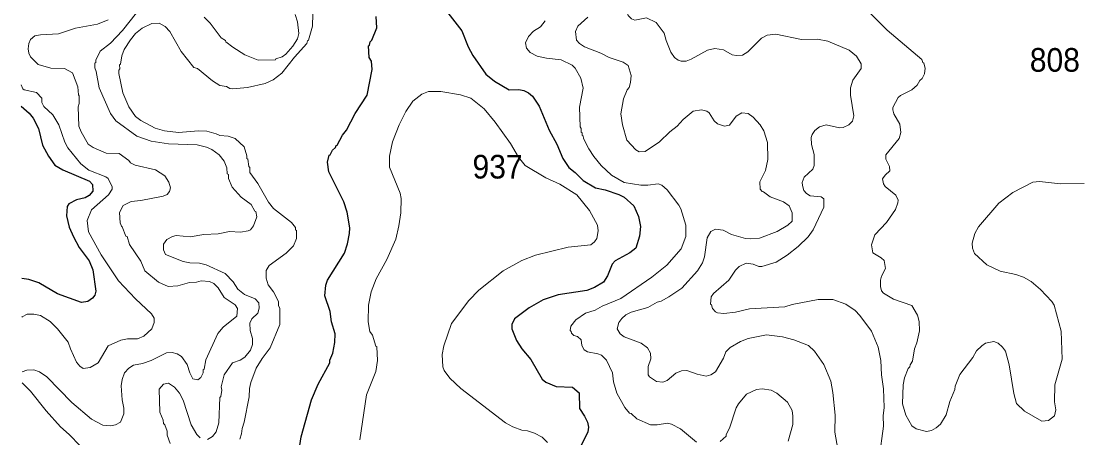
# Model space of a CAD drawing. Extents: x 447.8 to 473.9, y 7733.1 to 7760.8.
# Drawn here: x 447.796 to 451.389, y 7753.347 to 7754.756 of the extents above; entities that cross this region are included whole.
import ezdxf

# ---------------------------------------------------------------- set-up
doc = ezdxf.new("R2010")
doc.units = 0
doc.header["$LTSCALE"] = 0.032
doc.layers.add('1', color=7, linetype='Continuous', lineweight=25)
doc.layers.add('2', color=7, linetype='Continuous', lineweight=13)
doc.layers.add('21', color=7, linetype='Continuous')

msp = doc.modelspace()

# ---------------------------------------------------------------- linework, layer by layer
at = {"layer": '1'}
for points in [[(449.2047, 7754.832), (449.2874, 7754.724), (449.309, 7754.67), (449.325, 7754.6405), (449.3687, 7754.5776), (449.3987, 7754.5529), (449.4484, 7754.5245), (449.4803, 7754.5252), (449.4977, 7754.5213), (449.5137, 7754.5134), (449.5265, 7754.5021), (449.5489, 7754.469), (449.5831, 7754.3878), (449.6096, 7754.3397), (449.6296, 7754.2916), (449.65, 7754.2618), (449.6712, 7754.2446), (449.6981, 7754.2169), (449.7403, 7754.1925), (449.7729, 7754.1859), (449.8195, 7754.1704), (449.8368, 7754.1609), (449.8695, 7754.1313), (449.8858, 7754.0951), (449.8922, 7754.0613), (449.8891, 7754.029), (449.8762, 7753.9882), (449.8558, 7753.9731), (449.8069, 7753.9458), (449.7964, 7753.9339), (449.7805, 7753.8951)], [(448.7366, 7753.2995), (448.7445, 7753.3506), (448.7791, 7753.4747), (448.8013, 7753.5286), (448.8406, 7753.6001), (448.8408, 7753.6098), (448.8511, 7753.633), (448.8584, 7753.6687), (448.8591, 7753.6985), (448.8471, 7753.7392), (448.8424, 7753.7738), (448.8246, 7753.8273), (448.8279, 7753.8627), (448.8328, 7753.8802), (448.8903, 7753.9714), (448.9008, 7754.0034), (448.908, 7754.0383), (448.9088, 7754.0567), (448.8998, 7754.11), (448.8878, 7754.1447), (448.8375, 7754.2471), (448.8335, 7754.2794), (448.8392, 7754.303), (448.8424, 7754.3044), (448.8504, 7754.3198), (448.8601, 7754.3287), (448.8623, 7754.3356), (448.8655, 7754.3364), (448.8838, 7754.3702), (448.8973, 7754.3881), (448.9264, 7754.4445), (448.9673, 7754.5055), (448.9841, 7754.5925), (448.982, 7754.6211), (448.9744, 7754.6339), (448.9722, 7754.6731), (448.9753, 7754.6755), (448.977, 7754.6863), (448.9831, 7754.6925), (448.9995, 7754.7342), (448.998, 7754.7722)], [(447.7967, 7754.4686), (447.8232, 7754.4452), (447.8371, 7754.4282), (447.8547, 7754.3929), (447.8682, 7754.337), (447.8884, 7754.2999), (447.91, 7754.2697), (447.9372, 7754.2539), (448.0275, 7754.2151), (448.0374, 7754.2038), (448.0391, 7754.1817), (448.0261, 7754.1669), (448.0134, 7754.159), (447.9839, 7754.1514), (447.9575, 7754.1388), (447.9516, 7754.1292), (447.9494, 7754.0977), (447.9589, 7754.0593), (447.973, 7754.0265), (447.9928, 7753.9911), (448.0262, 7753.9457), (448.039, 7753.9155), (448.0495, 7753.8434), (448.0461, 7753.8292), (448.0373, 7753.8189), (448.0222, 7753.808), (448.001, 7753.8047), (447.9187, 7753.8339), (447.8556, 7753.8706), (447.8225, 7753.8823), (447.7985, 7753.8852)], [(449.7805, 7753.8951), (449.7674, 7753.8738), (449.7366, 7753.8549), (449.7104, 7753.8448), (449.6138, 7753.8303), (449.5634, 7753.8141)], [(449.5634, 7753.8141), (449.5159, 7753.7861), (449.4662, 7753.7495), (449.4565, 7753.7296), (449.4571, 7753.7156), (449.4727, 7753.6761), (449.4913, 7753.6478), (449.5214, 7753.6119), (449.5595, 7753.5452), (449.5717, 7753.5348), (449.6067, 7753.5201), (449.6626, 7753.5185), (449.6852, 7753.4994), (449.6856, 7753.4459), (449.7034, 7753.4203), (449.7127, 7753.3994), (449.716, 7753.3826), (449.7143, 7753.367), (449.6856, 7753.3097)]]:
    msp.add_lwpolyline(points, dxfattribs=at)
at = {"layer": '2'}
for points in [[(449.9451, 7754.7519), (449.9132, 7754.7673), (449.8731, 7754.7592), (449.8618, 7754.7637), (449.8512, 7754.7755), (449.8467, 7754.7911)], [(448.0909, 7754.7611), (448.0546, 7754.7461), (447.9805, 7754.7322), (447.9226, 7754.7134), (447.8615, 7754.7105), (447.8422, 7754.7064), (447.8279, 7754.6947), (447.8226, 7754.6812), (447.8203, 7754.663), (447.8225, 7754.6485), (447.8282, 7754.6361), (447.8537, 7754.61), (447.8966, 7754.5972), (447.9425, 7754.5965), (447.9702, 7754.5819), (447.9878, 7754.534), (447.9901, 7754.5069), (447.9926, 7754.5041), (447.9926, 7754.478), (447.9895, 7754.4667), (447.9919, 7754.4006), (447.9989, 7754.382), (448.0235, 7754.3405), (448.0397, 7754.3285), (448.084, 7754.3097), (448.1284, 7754.3087), (448.1609, 7754.2847), (448.1667, 7754.2773), (448.1825, 7754.2693), (448.2514, 7754.2535)], [(448.1869, 7754.7844), (448.1388, 7754.7251), (448.099, 7754.6821), (448.0635, 7754.6546), (448.0488, 7754.6243), (448.0487, 7754.6162), (448.0456, 7754.6139), (448.0456, 7754.5983)], [(448.7829, 7754.7814), (448.7822, 7754.7399), (448.7685, 7754.6916), (448.7653, 7754.6899), (448.7628, 7754.6808), (448.721, 7754.6348), (448.6787, 7754.5807), (448.6493, 7754.5578), (448.6221, 7754.5456), (448.5623, 7754.5322), (448.513, 7754.5269), (448.5023, 7754.5286), (448.4909, 7754.5349), (448.4684, 7754.5391), (448.4434, 7754.5541), (448.3926, 7754.5957), (448.381, 7754.5998), (448.3378, 7754.6532), (448.2997, 7754.721), (448.2831, 7754.7382), (448.2638, 7754.7497)], [(448.7237, 7754.7791), (448.7316, 7754.7536), (448.7355, 7754.7142), (448.7313, 7754.6968), (448.7161, 7754.6717), (448.6923, 7754.6449), (448.68, 7754.6357), (448.6581, 7754.6285), (448.657, 7754.6253), (448.5987, 7754.6239), (448.5531, 7754.6426), (448.5126, 7754.668), (448.4893, 7754.6861), (448.4874, 7754.6907), (448.4727, 7754.7001), (448.4365, 7754.7499), (448.4161, 7754.7695)], [(449.6859, 7754.4656), (449.6983, 7754.5296), (449.6902, 7754.5632), (449.6715, 7754.5975), (449.6612, 7754.6071), (449.6237, 7754.626), (449.5743, 7754.6311), (449.5428, 7754.6379), (449.5187, 7754.65), (449.5062, 7754.6645), (449.5037, 7754.6836), (449.5131, 7754.7047), (449.5298, 7754.723), (449.5536, 7754.7372), (449.5697, 7754.7579)], [(449.9156, 7753.6515), (449.8949, 7753.667), (449.8373, 7753.6882), (449.8237, 7753.6987), (449.8138, 7753.715), (449.8192, 7753.7366), (449.8296, 7753.7507), (449.8433, 7753.7623), (449.8606, 7753.7718), (449.917, 7753.7872), (449.9484, 7753.8054), (449.9621, 7753.8095), (449.9888, 7753.824), (450.0323, 7753.8532), (450.0856, 7753.912), (450.102, 7753.9386), (450.1089, 7753.9588), (450.1175, 7754.0236), (450.1305, 7754.0449), (450.1464, 7754.0531), (450.1721, 7754.049), (450.2008, 7754.0344), (450.2479, 7754.0211), (450.2651, 7754.0194), (450.2953, 7754.0224), (450.3546, 7754.0453), (450.3912, 7754.0661), (450.4053, 7754.0793), (450.4052, 7754.1074), (450.3957, 7754.1321), (450.3759, 7754.1447), (450.3312, 7754.162), (450.3086, 7754.1795), (450.3037, 7754.18), (450.2976, 7754.1885), (450.2965, 7754.2125), (450.315, 7754.2508), (450.3236, 7754.2884), (450.322, 7754.3464), (450.3099, 7754.3852), (450.2977, 7754.4061), (450.2742, 7754.432), (450.2568, 7754.4436), (450.2351, 7754.4465), (450.216, 7754.4352), (450.1931, 7754.4044), (450.1771, 7754.401), (450.1534, 7754.4085), (450.1415, 7754.4197), (450.1247, 7754.4466), (450.1168, 7754.4522), (450.0994, 7754.4563), (450.0704, 7754.4514), (450.0366, 7754.4242), (450.0163, 7754.4006), (449.9915, 7754.3815), (449.9562, 7754.3483), (449.9084, 7754.3153), (449.8874, 7754.3138), (449.8764, 7754.3215), (449.8459, 7754.3536), (449.8315, 7754.4055), (449.8259, 7754.4423), (449.835, 7754.4933), (449.847, 7754.5235), (449.8537, 7754.5322), (449.8588, 7754.5491), (449.8604, 7754.5722), (449.8505, 7754.6059), (449.834, 7754.6177), (449.7859, 7754.6337), (449.7577, 7754.6478), (449.7025, 7754.6695), (449.6859, 7754.6812), (449.6756, 7754.6926), (449.6728, 7754.7219), (449.6806, 7754.7398), (449.7144, 7754.7694)], [(450.7004, 7753.2774), (450.7148, 7753.3861), (450.7132, 7753.4214), (450.7173, 7753.4495), (450.7148, 7753.5128), (450.7076, 7753.5603), (450.706, 7753.6087), (450.6971, 7753.6539), (450.6747, 7753.7076), (450.6348, 7753.7611), (450.6192, 7753.7775), (450.5875, 7753.7986), (450.5432, 7753.815), (450.4932, 7753.815), (450.4056, 7753.7975), (450.381, 7753.7901), (450.2608, 7753.7829), (450.2136, 7753.7718), (450.1739, 7753.7678), (450.1525, 7753.77), (450.146, 7753.7732), (450.1366, 7753.7844), (450.1328, 7753.7964), (450.1297, 7753.7985), (450.1313, 7753.8238), (450.1391, 7753.8348), (450.1918, 7753.8804), (450.214, 7753.9139), (450.2266, 7753.9264), (450.25, 7753.9377), (450.2733, 7753.9338), (450.2927, 7753.9266), (450.303, 7753.9265), (450.3511, 7753.941), (450.389, 7753.9643), (450.4265, 7753.9941), (450.4596, 7754.0264), (450.4772, 7754.0501), (450.5129, 7754.1273), (450.5126, 7754.155), (450.5042, 7754.1622), (450.4672, 7754.1652), (450.4544, 7754.1733), (450.4455, 7754.183), (450.4402, 7754.2), (450.44, 7754.2109), (450.4468, 7754.229), (450.476, 7754.2562), (450.48, 7754.2685), (450.4807, 7754.3051), (450.4712, 7754.3395), (450.47, 7754.3627), (450.4729, 7754.3724), (450.4822, 7754.3867), (450.4986, 7754.3994), (450.5209, 7754.4051), (450.5658, 7754.3954), (450.5782, 7754.3961), (450.5979, 7754.4053), (450.6102, 7754.4182), (450.6146, 7754.4366), (450.6026, 7754.5065), (450.6026, 7754.5308), (450.6113, 7754.5563), (450.6393, 7754.5966), (450.6394, 7754.6123), (450.6237, 7754.6379), (450.5988, 7754.6578), (450.5267, 7754.6892), (450.4911, 7754.696), (450.4368, 7754.6944), (450.3504, 7754.7121), (450.321, 7754.7089), (450.3023, 7754.6991), (450.2561, 7754.6524), (450.2373, 7754.6413), (450.2172, 7754.6399), (450.2027, 7754.6428), (450.1734, 7754.6592), (450.144, 7754.6639), (450.1191, 7754.6579), (450.0642, 7754.628), (450.0468, 7754.6213), (450.0296, 7754.6213), (450.0195, 7754.6245), (450.0076, 7754.6337), (449.9948, 7754.6513), (449.9788, 7754.6914), (449.9724, 7754.7155), (449.9451, 7754.7519)], [(450.7118, 7754.2224), (450.7209, 7754.2353), (450.7363, 7754.2497), (450.7356, 7754.2644), (450.7229, 7754.2899), (450.723, 7754.3039), (450.7676, 7754.3595), (450.7734, 7754.3792), (450.7705, 7754.4079), (450.7502, 7754.4424), (450.7461, 7754.4567), (450.747, 7754.4642), (450.7645, 7754.4985), (450.7719, 7754.5049), (450.8113, 7754.524), (450.8293, 7754.5396), (450.8379, 7754.5552), (450.8462, 7754.5623), (450.8541, 7754.5779), (450.8557, 7754.5969), (450.8511, 7754.6144), (450.8479, 7754.6161), (450.8447, 7754.6267), (450.7275, 7754.7257), (450.6681, 7754.7851)], [(448.2638, 7754.7497), (448.2381, 7754.7488), (448.2053, 7754.733), (448.1832, 7754.715), (448.1658, 7754.6933), (448.1454, 7754.6601)], [(448.1454, 7754.6601), (448.1371, 7754.6389), (448.1321, 7754.6106), (448.129, 7754.6082), (448.1303, 7754.5956), (448.1273, 7754.5901), (448.1273, 7754.5789), (448.1401, 7754.5142), (448.1608, 7754.467), (448.1832, 7754.4334), (448.2017, 7754.4199), (448.25, 7754.3948), (448.2809, 7754.385), (448.3287, 7754.3802), (448.3963, 7754.3849), (448.4251, 7754.3842), (448.4568, 7754.3755), (448.4687, 7754.3693), (448.4973, 7754.3674), (448.5203, 7754.3599), (448.5506, 7754.3308), (448.5601, 7754.3012), (448.5602, 7754.2914), (448.5633, 7754.2892), (448.5666, 7754.265), (448.5697, 7754.2612), (448.5701, 7754.2448), (448.597, 7754.207), (448.6329, 7754.1441), (448.6505, 7754.1224), (448.7117, 7754.0754), (448.7251, 7754.0586), (448.7253, 7754.0503), (448.7284, 7754.0479), (448.7283, 7754.0207), (448.7178, 7753.9967), (448.693, 7753.9712), (448.6351, 7753.93), (448.6259, 7753.9133), (448.6259, 7753.8864), (448.6322, 7753.8643), (448.6501, 7753.8412), (448.6675, 7753.8075), (448.6676, 7753.7936), (448.6723, 7753.7849), (448.6716, 7753.7299), (448.6389, 7753.651), (448.6116, 7753.6156), (448.5919, 7753.5827), (448.5731, 7753.5343), (448.5688, 7753.5133), (448.5681, 7753.4856), (448.5506, 7753.3993), (448.5439, 7753.3787), (448.5425, 7753.3606), (448.5363, 7753.342)], [(448.0456, 7754.5983), (448.0506, 7754.5858), (448.0607, 7754.5304), (448.0983, 7754.4445), (448.1165, 7754.419), (448.1878, 7754.3678)], [(447.7989, 7753.7555), (447.7995, 7753.7558), (447.8163, 7753.7653), (447.8394, 7753.7652), (447.8618, 7753.7602), (447.8943, 7753.7402), (447.9193, 7753.7151), (447.9555, 7753.6699), (447.9628, 7753.6478), (447.9839, 7753.6027), (447.9952, 7753.5887), (448.0066, 7753.581), (448.0301, 7753.5844), (448.0573, 7753.6008), (448.0908, 7753.6579), (448.1341, 7753.6772), (448.1561, 7753.6811), (448.1901, 7753.6812), (448.212, 7753.6912), (448.2382, 7753.7153), (448.2459, 7753.7373), (448.246, 7753.7512), (448.2378, 7753.766), (448.1833, 7753.8167), (448.1258, 7753.8783), (448.0676, 7753.9655), (448.0244, 7754.0441), (448.0191, 7754.0816), (448.0341, 7754.1182), (448.0918, 7754.1683), (448.1041, 7754.1876), (448.1048, 7754.1954), (448.091, 7754.2236), (448.0828, 7754.2293), (448.0248, 7754.2519), (447.9977, 7754.2741), (447.9542, 7754.3273), (447.9443, 7754.3471), (447.9235, 7754.4061), (447.903, 7754.4392), (447.8728, 7754.4682), (447.866, 7754.4807), (447.8659, 7754.496), (447.8477, 7754.5149), (447.8064, 7754.5239), (447.8018, 7754.5272), (447.7965, 7754.5409)], [(448.9722, 7753.795), (448.9813, 7753.8409), (448.9977, 7753.8845), (449.0342, 7753.9495), (449.0642, 7754.0191), (449.0747, 7754.0644), (449.0812, 7754.108), (449.0826, 7754.156), (449.0795, 7754.1749), (449.0434, 7754.2626), (449.0428, 7754.2999), (449.0532, 7754.3483), (449.0754, 7754.4055), (449.098, 7754.4506), (449.1221, 7754.4852), (449.1523, 7754.5096), (449.175, 7754.5188), (449.2171, 7754.5181), (449.2836, 7754.5071), (449.3184, 7754.4963), (449.3628, 7754.4592), (449.4008, 7754.4149), (449.4522, 7754.3423), (449.4799, 7754.2957), (449.5023, 7754.2684), (449.5715, 7754.2264), (449.6198, 7754.2054), (449.677, 7754.1689), (449.7196, 7754.1162), (449.7464, 7754.0659), (449.7495, 7754.0473), (449.7441, 7754.0207), (449.7369, 7754.0093), (449.7244, 7754.0002), (449.648, 7753.9912), (449.5371, 7753.9651), (449.4913, 7753.9463), (449.428, 7753.9115), (449.3447, 7753.8468), (449.311, 7753.8108), (449.2528, 7753.734), (449.2272, 7753.6578), (449.2207, 7753.6282), (449.223, 7753.5869), (449.2275, 7753.5746), (449.2471, 7753.5489), (449.2847, 7753.5136), (449.436, 7753.3971), (449.46, 7753.3836), (449.4912, 7753.3727), (449.5105, 7753.3709), (449.5332, 7753.363), (449.5596, 7753.3484), (449.5779, 7753.3311)], [(449.6952, 7754.3701), (449.6951, 7754.3783), (449.692, 7754.3812), (449.6919, 7754.3934), (449.6878, 7754.3987), (449.6859, 7754.4656)], [(448.1878, 7754.3678), (448.2367, 7754.3504), (448.2953, 7754.3417), (448.3918, 7754.3384), (448.4238, 7754.3304), (448.4415, 7754.3224), (448.4667, 7754.3044), (448.4831, 7754.2823), (448.4928, 7754.2596), (448.4937, 7754.2402), (448.4975, 7754.2381), (448.4977, 7754.2246), (448.5105, 7754.1944), (448.541, 7754.1608), (448.5747, 7754.1362), (448.5874, 7754.1136), (448.5905, 7754.1123), (448.5938, 7754.094), (448.5831, 7754.0636), (448.5725, 7754.0505), (448.5643, 7754.0465), (448.5388, 7754.0427), (448.5009, 7754.0442), (448.463, 7754.0371), (448.4146, 7754.0347), (448.3682, 7754.0267), (448.3207, 7754.0315), (448.3085, 7754.0282), (448.2897, 7754.0181), (448.278, 7754.0023), (448.278, 7753.9825), (448.2847, 7753.9673), (448.3447, 7753.943), (448.3671, 7753.9385), (448.3998, 7753.9376), (448.4223, 7753.9325), (448.4865, 7753.9022), (448.5136, 7753.875), (448.5301, 7753.8492), (448.5527, 7753.8315), (448.5887, 7753.8168), (448.6002, 7753.8035), (448.6017, 7753.7852), (448.597, 7753.769), (448.5769, 7753.7491), (448.5699, 7753.7346), (448.5715, 7753.7094), (448.5794, 7753.6831), (448.5793, 7753.6622), (448.5727, 7753.6433), (448.5534, 7753.6196), (448.538, 7753.6096), (448.5117, 7753.6003), (448.4834, 7753.5599), (448.4736, 7753.5197), (448.4752, 7753.5077), (448.4719, 7753.486), (448.4688, 7753.4829), (448.4655, 7753.3975), (448.4558, 7753.3667), (448.4434, 7753.3512), (448.4273, 7753.3407)], [(450.0825, 7753.3321), (450.0276, 7753.3769), (449.9976, 7753.3927), (449.9837, 7753.3967), (449.9484, 7753.391), (449.926, 7753.391), (449.88, 7753.4111), (449.8605, 7753.4292), (449.855, 7753.4307), (449.8396, 7753.4488), (449.8125, 7753.4978), (449.801, 7753.5365), (449.7974, 7753.5668), (449.7773, 7753.6096), (449.7609, 7753.6265), (449.7481, 7753.6314), (449.7127, 7753.6372), (449.7017, 7753.6445), (449.6935, 7753.6594), (449.6915, 7753.6783), (449.6791, 7753.6891), (449.6665, 7753.6932), (449.6586, 7753.701), (449.6582, 7753.706), (449.6544, 7753.7095), (449.6567, 7753.724), (449.6732, 7753.7457), (449.7064, 7753.7685), (449.7394, 7753.7787), (449.7628, 7753.7919), (449.8253, 7753.8176), (449.9313, 7753.8899), (449.982, 7753.9311), (450.0296, 7753.986), (450.0462, 7754.0278), (450.0462, 7754.0659), (450.029, 7754.1209), (450.0218, 7754.1342), (449.9827, 7754.1856), (449.9647, 7754.202), (449.952, 7754.2063), (449.9171, 7754.2015), (449.8939, 7754.2015), (449.8375, 7754.2104), (449.7939, 7754.2358), (449.7589, 7754.2684), (449.7346, 7754.2981), (449.7175, 7754.3243), (449.6997, 7754.3598), (449.6983, 7754.3679), (449.6952, 7754.3701)], [(448.2514, 7754.2535), (448.2824, 7754.2336), (448.2955, 7754.2121), (448.302, 7754.1925), (448.298, 7754.1798), (448.2909, 7754.1697)], [(451.3942, 7754.2071), (451.3138, 7754.2063), (451.2429, 7754.2142), (451.2198, 7754.2118), (451.1522, 7754.1772), (451.1057, 7754.1402), (451.0364, 7754.0601), (451.024, 7754.038), (451.0154, 7754.0054), (451.0157, 7753.9888), (451.0227, 7753.9699), (451.0645, 7753.9319), (451.1102, 7753.91), (451.1628, 7753.8992), (451.1889, 7753.8898), (451.2144, 7753.876), (451.246, 7753.8482), (451.2845, 7753.8081), (451.2922, 7753.796), (451.3167, 7753.7072), (451.3191, 7753.6123), (451.2952, 7753.5256), (451.2936, 7753.468), (451.2984, 7753.4415), (451.2934, 7753.4207), (451.2735, 7753.4051), (451.2503, 7753.4031), (451.192, 7753.4373), (451.1654, 7753.4632), (451.1557, 7753.4965), (451.1404, 7753.5933), (451.1272, 7753.64), (451.118, 7753.6531), (451.1026, 7753.6674), (451.0883, 7753.6731), (451.0606, 7753.6666), (451.0474, 7753.6582), (451.0299, 7753.641), (451.0172, 7753.6181), (450.973, 7753.5615), (450.9578, 7753.5215), (450.9566, 7753.5106), (450.9397, 7753.4695), (450.9272, 7753.4246), (450.908, 7753.3933), (450.8932, 7753.3806), (450.8772, 7753.3715), (450.8605, 7753.3685), (450.8252, 7753.3772), (450.8113, 7753.3874), (450.7902, 7753.423), (450.779, 7753.4612), (450.7814, 7753.526), (450.7858, 7753.5499), (450.7978, 7753.5809), (450.8044, 7753.5867), (450.8046, 7753.5936), (450.8126, 7753.6056), (450.8196, 7753.648), (450.8279, 7753.6686), (450.8366, 7753.7088), (450.835, 7753.7404), (450.8298, 7753.7618), (450.8104, 7753.7944), (450.7483, 7753.8155), (450.7147, 7753.8361), (450.7084, 7753.8441), (450.7052, 7753.8584), (450.7052, 7753.8799), (450.7084, 7753.8933), (450.7212, 7753.9193), (450.7174, 7753.9465), (450.7073, 7753.956), (450.6782, 7753.9729), (450.674, 7753.9991), (450.6853, 7754.0332), (450.7252, 7754.0749), (450.755, 7754.1191), (450.7637, 7754.1412)], [(450.7637, 7754.1412), (450.7644, 7754.1509), (450.7562, 7754.1679), (450.7204, 7754.1965), (450.7143, 7754.2062), (450.7118, 7754.2224)], [(448.2909, 7754.1697), (448.277, 7754.1639), (448.2013, 7754.1493), (448.1682, 7754.1468), (448.142, 7754.1326), (448.129, 7754.1092), (448.1319, 7754.0741), (448.1354, 7754.0623), (448.1384, 7754.061), (448.151, 7754.0289), (448.1548, 7754.0275), (448.1633, 7754.0005), (448.201, 7753.944), (448.2151, 7753.9115), (448.2609, 7753.8729), (448.2937, 7753.8592), (448.326, 7753.8607), (448.3661, 7753.8727), (448.3902, 7753.8736), (448.4059, 7753.8775), (448.4333, 7753.8757), (448.4484, 7753.8689), (448.4633, 7753.8541), (448.4838, 7753.8215), (448.5202, 7753.7964), (448.528, 7753.7842), (448.5262, 7753.758), (448.4805, 7753.721), (448.4615, 7753.7001), (448.4216, 7753.6109), (448.4158, 7753.579), (448.4127, 7753.5766), (448.4126, 7753.5661), (448.4045, 7753.5513), (448.3942, 7753.5434), (448.3772, 7753.5462), (448.3667, 7753.5664), (448.3581, 7753.5944), (448.3389, 7753.6218), (448.3247, 7753.6313), (448.3071, 7753.6354), (448.2883, 7753.6347), (448.2358, 7753.6086), (448.2065, 7753.598), (448.1765, 7753.5926), (448.1607, 7753.5823), (448.1461, 7753.5664), (448.1378, 7753.5436), (448.1344, 7753.5229), (448.1386, 7753.4757), (448.1441, 7753.4471), (448.1433, 7753.4278), (448.1327, 7753.3998), (448.1157, 7753.3909), (448.1, 7753.3878), (448.073, 7753.3894), (448.0341, 7753.4096), (447.968, 7753.4661), (447.8835, 7753.5529), (447.8582, 7753.5696), (447.8386, 7753.5769), (447.815, 7753.5761), (447.7995, 7753.5695)], [(448.9768, 7753.7059), (448.9706, 7753.7389), (448.9722, 7753.795)], [(448.9426, 7753.34), (448.9648, 7753.4923), (448.9971, 7753.5714), (449.0027, 7753.6079), (448.9995, 7753.6541), (448.9962, 7753.6566), (448.985, 7753.6937), (448.9768, 7753.7059)], [(450.5608, 7753.3079), (450.5497, 7753.3654), (450.5512, 7753.4237), (450.5432, 7753.5003), (450.5361, 7753.5381), (450.5127, 7753.595), (450.4816, 7753.64), (450.4605, 7753.6591), (450.4115, 7753.6788), (450.3733, 7753.6883), (450.3189, 7753.6949), (450.2573, 7753.6833), (450.2304, 7753.6726), (450.1964, 7753.6525), (450.1809, 7753.6376), (450.1732, 7753.616), (450.1461, 7753.5703), (450.131, 7753.5597), (450.1146, 7753.5554), (450.0837, 7753.5616), (450.0494, 7753.5745), (450.0309, 7753.5738), (450.0116, 7753.5653), (449.9823, 7753.541), (449.9683, 7753.5345), (449.9464, 7753.5374), (449.9224, 7753.5533)], [(449.9224, 7753.5533), (449.9181, 7753.5594), (449.9189, 7753.5884), (449.9277, 7753.6139), (449.926, 7753.6335), (449.9156, 7753.6515)], [(447.9956, 7753.3191), (447.9592, 7753.3579), (447.9296, 7753.3843), (447.881, 7753.4386), (447.8281, 7753.5051), (447.8005, 7753.5318), (447.7996, 7753.5323)], [(448.4025, 7753.3469), (448.3904, 7753.3582), (448.3722, 7753.3909), (448.3449, 7753.4737), (448.3318, 7753.4982), (448.3149, 7753.5176), (448.295, 7753.5319), (448.2782, 7753.5288), (448.2636, 7753.5109), (448.2655, 7753.4332), (448.2768, 7753.4065), (448.278, 7753.3954), (448.2827, 7753.3904), (448.2908, 7753.3698), (448.2909, 7753.356), (448.3002, 7753.3275)], [(450.3926, 7753.3352), (450.4078, 7753.3917), (450.4085, 7753.4198), (450.4053, 7753.4388), (450.39, 7753.4677), (450.3534, 7753.4978), (450.3342, 7753.5076), (450.3037, 7753.512), (450.2854, 7753.5097), (450.2517, 7753.4947), (450.2241, 7753.4621), (450.2165, 7753.4477), (450.1935, 7753.3791), (450.1826, 7753.3581), (450.1825, 7753.3521), (450.1626, 7753.3344)]]:
    msp.add_lwpolyline(points, dxfattribs=at)

# ---------------------------------------------------------------- texts
at = {"layer": '21', "width": 0.95}
for s, p in [('808', (451.21, 7754.5853)), ('937', (449.3239, 7754.224))]:
    msp.add_text(s, height=0.08, dxfattribs=at).set_placement(p)

doc.saveas('drawing.dxf')
